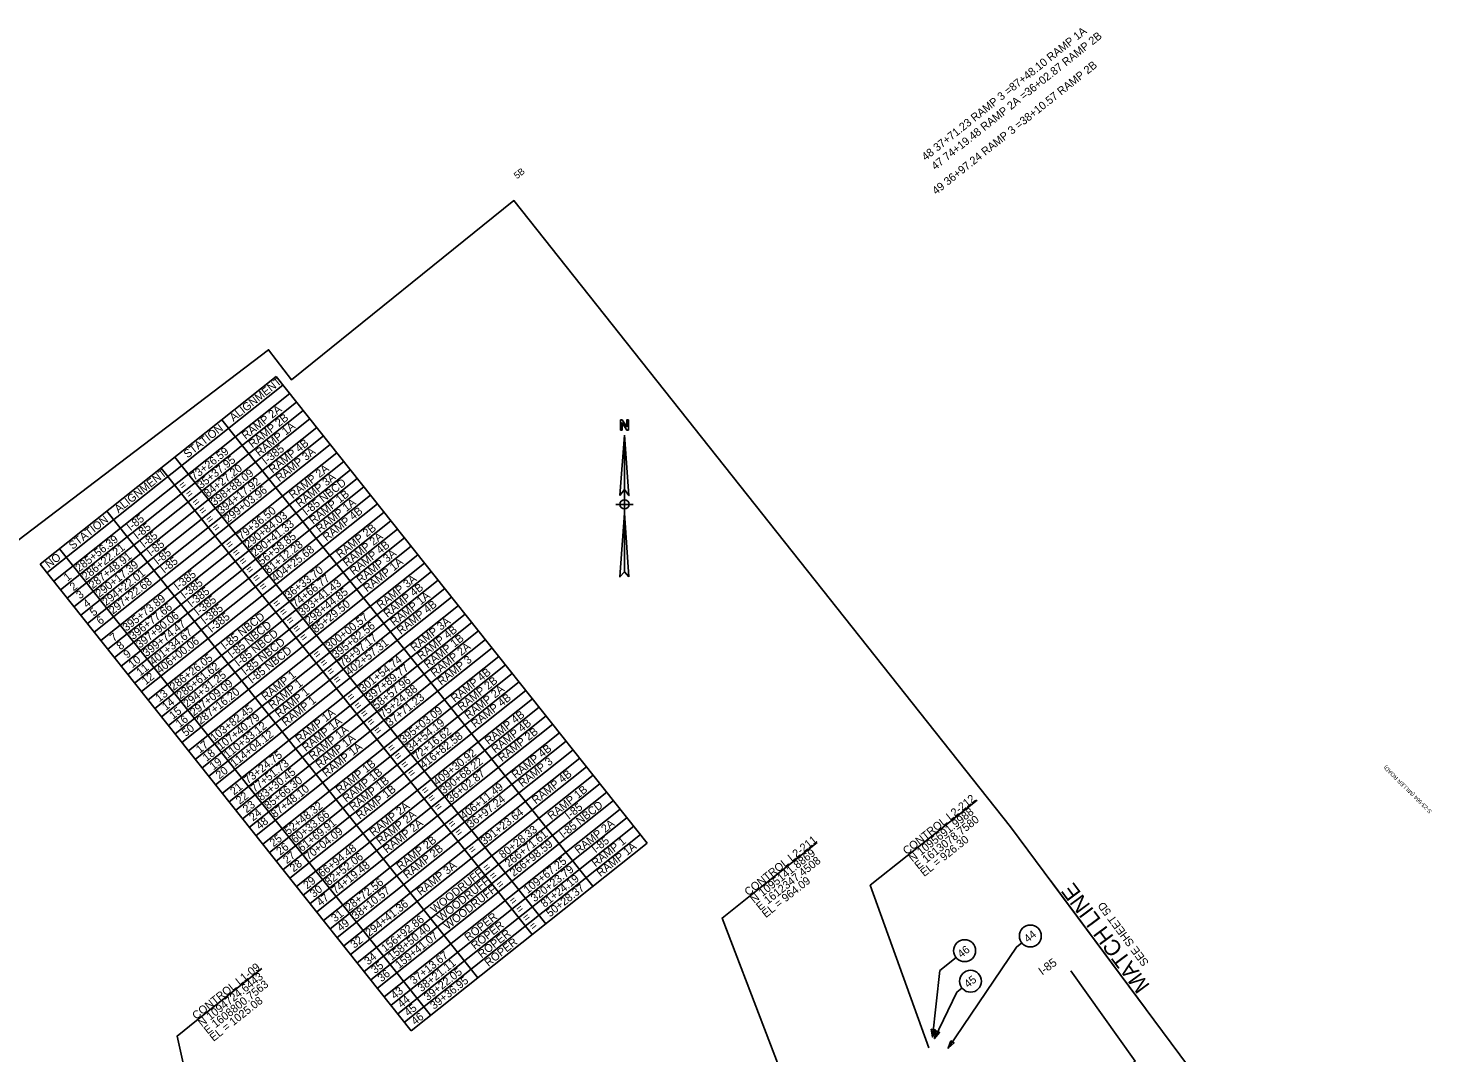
# Model space of a CAD drawing. Extents: x 1600294 to 1616097, y 1087057 to 1101809.
# Drawn here: x 1607677 to 1616097, y 1095661 to 1101809 of the extents above; entities that cross this region are included whole.
import ezdxf

# ---------------------------------------------------------------- set-up
doc = ezdxf.new("R2010")
doc.units = 0
for name, color, linetype in [('LABEL', 7, 'Continuous'), ('Level 1', 7, 'Continuous'), ('Plan_Clip', 7, 'Continuous'), ('RD_SHT_Bndy', 7, 'Continuous'), ('RD_SHT_MatchLine', 7, 'Continuous'), ('RD_SHT_TX', 7, 'Continuous'), ('RD_TX_Misc2', 7, 'Continuous'), ('RD_TX_RoadID', 7, 'Continuous')]:
    doc.layers.add(name, color=color, linetype=linetype)

msp = doc.modelspace()

# ---------------------------------------------------------------- linework, layer by layer
at = {"layer": 'LABEL'}
for points in [[(1613637.3, 1096321.6), (1613605.4, 1096296.3), (1613195.5, 1095689.7)], [(1613242.8, 1096233.5), (1613144.8, 1096155.6), (1613100.8, 1095756.4)], [(1613278.5, 1096050.3), (1613246.6, 1096025), (1613112.8, 1095747.6)]]:
    msp.add_lwpolyline(points, dxfattribs=at)
for points in [[(1613093.6, 1095803.4), (1613100.8, 1095756.4), (1613118, 1095800.7)], [(1613121.6, 1095794.2), (1613112.8, 1095747.6), (1613143.8, 1095783.6)], [(1613211, 1095734.7), (1613195.5, 1095689.7), (1613231.4, 1095720.9)]]:
    msp.add_lwpolyline(points, close=True, dxfattribs=at)
for centre in [(1613688.7, 1096362.5), (1613294.2, 1096274.4), (1613329.9, 1096091.2)]:
    msp.add_circle(centre, 65.7, dxfattribs=at)
at = {"layer": 'Level 1'}
for p, q in [((1611253.9, 1099366.7), (1611226.5, 1099004.2)), ((1611253.9, 1099041.4), (1611226.5, 1099004.2)), ((1611253.9, 1099041.4), (1611253.9, 1098898.7)), ((1611306.1, 1098951.6), (1611202.3, 1098951.6)), ((1611253.9, 1098898.7), (1611281.2, 1098516)), ((1611281.2, 1098516), (1611253.9, 1098546.6))]:
    msp.add_line(p, q, dxfattribs=at)
msp.add_lwpolyline([(1611277.4, 1099397.3), (1611267.6, 1099397.3), (1611240.2, 1099441.1), (1611240.2, 1099434.5), (1611240.2, 1099397.3), (1611230.4, 1099397.3), (1611230.4, 1099458), (1611240.2, 1099458), (1611267.6, 1099417.6), (1611267.6, 1099420.8), (1611267.6, 1099458), (1611277.4, 1099458), (1611277.4, 1099397.3)], dxfattribs=at)
for points in [[(1611253.9, 1099366.7), (1611281.2, 1099004.2), (1611253.9, 1099041.4)], [(1611253.9, 1098898.7), (1611253.9, 1098546.6), (1611226.5, 1098516)]]:
    msp.add_lwpolyline(points, close=True, dxfattribs=at)
msp.add_circle((1611254.2, 1098951.6), 27.6, dxfattribs=at)
at = {"layer": 'Plan_Clip'}
msp.add_lwpolyline([(1600293.9, 1092641.5), (1602343.7, 1094579.4), (1605167, 1096872.5), (1609119.4, 1099879.5), (1609257.5, 1099698.1), (1610590.9, 1100773.5), (1613569.3, 1097017.7), (1614735.8, 1095448.6), (1612219.9, 1092822.8), (1611099.3, 1092347), (1604705.4, 1087056.6)], close=True, dxfattribs=at)
at = {"layer": 'RD_SHT_MatchLine'}
msp.add_line((1614379.1, 1095928.4), (1613808.6, 1096695.9), dxfattribs=at)
at = {"layer": 'RD_SHT_TX'}
for p, q in [((1613369.6, 1097178), (1612949.9, 1096844.1)), ((1612410.7, 1096924.3), (1611999.8, 1096597.4)), ((1609079.9, 1096167.9), (1608687.5, 1095855.7))]:
    msp.add_line(p, q, dxfattribs=at)
for points in [[(1612949.9, 1096844.1), (1612727.9, 1096667.5), (1613078.8, 1095692)], [(1611999.8, 1096597.4), (1611839.6, 1096470), (1612347.5, 1095141.9)], [(1614184.5, 1095506.8), (1614316.5, 1095611.8), (1613931.7, 1096153.5)], [(1608687.5, 1095855.7), (1608570.6, 1095762.7), (1608800.8, 1094724.6)]]:
    msp.add_lwpolyline(points, dxfattribs=at)
at = {"layer": 'RD_TX_Misc2'}
for p, q in [((1607749.8, 1098592.3), (1609165.3, 1099718.2)), ((1607790.3, 1098541.4), (1609205.7, 1099667.3)), ((1609165.3, 1099718.2), (1611390.7, 1096920.3)), ((1607830.7, 1098490.6), (1609246.2, 1099616.4)), ((1607871.2, 1098439.7), (1609286.6, 1099565.6)), ((1607911.7, 1098388.8), (1609327.1, 1099514.7)), ((1607952.1, 1098338), (1609367.6, 1099463.8)), ((1607992.6, 1098287.1), (1609408, 1099413)), ((1608839.7, 1099459.2), (1611065.1, 1096661.3)), ((1608033.1, 1098236.2), (1609448.5, 1099362.1)), ((1608073.5, 1098185.3), (1609489, 1099311.2)), ((1608114, 1098134.5), (1609529.4, 1099260.3)), ((1608154.4, 1098083.6), (1609569.9, 1099209.5)), ((1608474.7, 1099168.9), (1610700.1, 1096371)), ((1608556.4, 1099233.9), (1610781.9, 1096436.1)), ((1608194.9, 1098032.7), (1609610.3, 1099158.6)), ((1608235.4, 1097981.9), (1609650.8, 1099107.7)), ((1608275.8, 1097931), (1609691.3, 1099056.9)), ((1608316.3, 1097880.1), (1609731.7, 1099006)), ((1608149.1, 1098909.9), (1610374.5, 1096112)), ((1608356.8, 1097829.3), (1609772.2, 1098955.1)), ((1608397.2, 1097778.4), (1609812.7, 1098904.3)), ((1608437.7, 1097727.5), (1609853.1, 1098853.4)), ((1608478.1, 1097676.7), (1609893.6, 1098802.5)), ((1608518.6, 1097625.8), (1609934, 1098751.7)), ((1607865.8, 1098684.6), (1610091.3, 1095886.8)), ((1608559.1, 1097574.9), (1609974.5, 1098700.8)), ((1607749.8, 1098592.3), (1609975.3, 1095794.5)), ((1608599.5, 1097524), (1610015, 1098649.9)), ((1608640, 1097473.2), (1610055.4, 1098599)), ((1608680.5, 1097422.3), (1610095.9, 1098548.2)), ((1608720.9, 1097371.4), (1610136.4, 1098497.3)), ((1608761.4, 1097320.6), (1610176.8, 1098446.4)), ((1608801.9, 1097269.7), (1610217.3, 1098395.6)), ((1608842.3, 1097218.8), (1610257.8, 1098344.7)), ((1608882.8, 1097168), (1610298.2, 1098293.8)), ((1608923.2, 1097117.1), (1610338.7, 1098243)), ((1608963.7, 1097066.2), (1610379.1, 1098192.1)), ((1609004.2, 1097015.3), (1610419.6, 1098141.2)), ((1609044.6, 1096964.5), (1610460.1, 1098090.3)), ((1609085.1, 1096913.6), (1610500.5, 1098039.5)), ((1609125.6, 1096862.7), (1610541, 1097988.6)), ((1609166, 1096811.9), (1610581.5, 1097937.7)), ((1609206.5, 1096761), (1610621.9, 1097886.9)), ((1609246.9, 1096710.1), (1610662.4, 1097836)), ((1609287.4, 1096659.3), (1610702.8, 1097785.1)), ((1609327.9, 1096608.4), (1610743.3, 1097734.3)), ((1609368.3, 1096557.5), (1610783.8, 1097683.4)), ((1609408.8, 1096506.6), (1610824.2, 1097632.5)), ((1609449.3, 1096455.8), (1610864.7, 1097581.6)), ((1609489.7, 1096404.9), (1610905.2, 1097530.8)), ((1609530.2, 1096354), (1610945.6, 1097479.9)), ((1609570.6, 1096303.2), (1610986.1, 1097429)), ((1609611.1, 1096252.3), (1611026.5, 1097378.2)), ((1609651.6, 1096201.4), (1611067, 1097327.3)), ((1609692, 1096150.6), (1611107.5, 1097276.4)), ((1609732.5, 1096099.7), (1611147.9, 1097225.6)), ((1609773, 1096048.8), (1611188.4, 1097174.7)), ((1609813.4, 1095997.9), (1611228.9, 1097123.8)), ((1609853.9, 1095947.1), (1611269.3, 1097072.9)), ((1609894.4, 1095896.2), (1611309.8, 1097022.1)), ((1609934.8, 1095845.3), (1611350.3, 1096971.2)), ((1609975.3, 1095794.5), (1611390.7, 1096920.3))]:
    msp.add_line(p, q, dxfattribs=at)

# ---------------------------------------------------------------- texts
at = {"layer": 'LABEL'}
for s, p in [('44', (1613673.6, 1096320.2)), ('46', (1613274.7, 1096228.5)), ('45', (1613314.8, 1096048.9))]:
    msp.add_text(s, height=47.52, rotation=38.4995, dxfattribs=at).set_placement(p)
at = {"layer": 'RD_SHT_Bndy'}
msp.add_text('5B', height=40, rotation=38.4995, dxfattribs=at).set_placement((1610609.8, 1100901.4))
at = {"layer": 'RD_SHT_MatchLine'}
for s, height, p in [('MATCH LINE', 96, (1614409.2, 1096065.4)), ('SEE SHEET 5D', 48, (1614401.8, 1096203.3))]:
    msp.add_text(s, height=height, rotation=126.62559, dxfattribs=at).set_placement(p)
at = {"layer": 'RD_SHT_TX'}
for s, p in [('48 37+71.23 RAMP 3 =87+48.10 RAMP 1A', (1613060.3, 1101010.2)), ('47 74+19.48 RAMP 2A =36+02.87 RAMP 2B', (1613118.6, 1100954.6)), ('49 36+97.24 RAMP 3 =38+10.57 RAMP 2B', (1613123.3, 1100806.4)), ('CONTROL L2-212', (1612947.4, 1096847.3)), ('N 1095691.9988', (1612982.3, 1096803.4)), ('E 1613078.7580', (1613017.1, 1096759.6)), ('CONTROL L2-211', (1611997.3, 1096600.5)), ('EL = 926.30', (1613052, 1096715.8)), ('N 1095141.8869', (1612032.1, 1096556.7)), ('E 1612347.4508', (1612067, 1096512.9)), ('EL = 964.09', (1612101.9, 1096469.1)), ('CONTROL L1-09', (1608685, 1095858.8)), ('N 1094724.6443', (1608719.8, 1095815)), ('E 1608800.7563', (1608754.7, 1095771.2)), ('EL = 1025.08', (1608789.5, 1095727.3))]:
    msp.add_text(s, height=48, rotation=38.4995, dxfattribs=at).set_placement(p)
at = {"layer": 'RD_TX_Misc2'}
for s, p in [('ALIGNMENT', (1608909.2, 1099445.8)), ('RAMP 2A', (1608982.6, 1099338.5)), ('RAMP 2B', (1609023, 1099287.6)), ('STATION', (1608633.9, 1099226.8)), ('RAMP 1A', (1609063.5, 1099236.7)), ('RAMP 4B', (1609144.4, 1099135)), ('73+26.59', (1608674.3, 1099093.3)), ('35+37.95', (1608714.8, 1099042.4)), ('I-385', (1609104, 1099185.8)), ('RAMP 3A', (1609184.9, 1099084.1)), ('ALIGNMENT', (1608219.2, 1098897)), ('84+27.20', (1608755.2, 1098991.5)), ('398+88.09', (1608795.7, 1098940.7)), ('RAMP 2A', (1609265.8, 1098982.4)), ('=', (1608603.7, 1099037.5)), ('394+17.92', (1608836.2, 1098889.8)), ('RAMP 3A', (1609306.3, 1098931.5)), ('I-85 NBCD', (1609346.7, 1098880.6)), ('=', (1608644.1, 1098986.7)), ('299+03.96', (1608876.6, 1098838.9)), ('RAMP 1B', (1609387.2, 1098829.8)), ('=', (1608684.5, 1098935.9)), ('=', (1608724.3, 1098885.9)), ('79+36.50', (1608957.6, 1098737.2)), ('290+84.03', (1608998, 1098686.3)), ('RAMP 1A', (1609427.7, 1098778.9)), ('RAMP 4B', (1609468.1, 1098728)), ('STATION', (1607944.7, 1098678.6)), ('I-85', (1608292, 1098789.2)), ('I-85', (1608332.5, 1098738.3)), ('=', (1608765.9, 1098833.6)), ('=', (1608805.1, 1098784.2)), ('290+41.33', (1609038.5, 1098635.4)), ('RAMP 2B', (1609549, 1098626.3)), ('285+56.39', (1607983.7, 1098544)), ('I-85', (1608372.9, 1098687.4)), ('I-85', (1608413.4, 1098636.5)), ('56+58.85', (1609078.9, 1098584.6)), ('RAMP 2A', (1609589.5, 1098575.4)), ('286+22.21', (1608023.5, 1098494)), ('287+48.91', (1608064.7, 1098442.2)), ('I-85', (1608453.8, 1098585.7)), ('=', (1608885.8, 1098682.8)), ('=', (1608925.8, 1098632.5)), ('81+12.28', (1609119.4, 1098533.7)), ('404+25.68', (1609159.9, 1098482.8)), ('RAMP 4B', (1609630, 1098524.5)), ('RAMP 3A', (1609670.4, 1098473.7)), ('NO', (1607803.3, 1098566.2)), ('290+17.39', (1608105.1, 1098391.4)), ('I-85', (1608494.3, 1098534.8)), ('=', (1608966.2, 1098581.7)), ('=', (1609006.3, 1098531.4)), ('36+33.70', (1609240.8, 1098381.1)), ('RAMP 1A', (1609710.9, 1098422.8)), ('1', (1607913.7, 1098487.6)), ('294+22.01', (1608145.6, 1098340.5)), ('297+22.68', (1608186.1, 1098289.6)), ('I-385', (1608575.2, 1098433.1)), ('I-385', (1608615.7, 1098382.2)), ('=', (1609046.7, 1098480.6)), ('74+66.77', (1609281.3, 1098330.2)), ('393+41.43', (1609321.7, 1098279.3)), ('RAMP 3A', (1609791.8, 1098321.1)), ('2', (1607949.7, 1098430)), ('3', (1607988.6, 1098381.1)), ('395+73.89', (1608267, 1098187.9)), ('I-385', (1608656.2, 1098331.3)), ('I-385', (1608696.6, 1098280.5)), ('=', (1609086.7, 1098430.2)), ('298+44.85', (1609362.2, 1098228.5)), ('RAMP 4B', (1609832.3, 1098270.2)), ('RAMP 1A', (1609872.7, 1098219.3)), ('4', (1608029.9, 1098328.5)), ('5', (1608070.6, 1098277.8)), ('396+77.66', (1608307.4, 1098137)), ('I-385', (1608737.1, 1098229.6)), ('=', (1609168, 1098328)), ('=', (1609208.4, 1098277.2)), ('85+29.50', (1609402.7, 1098177.6)), ('RAMP 4B', (1609913.2, 1098168.4)), ('6', (1608110.4, 1098227.3)), ('397+90.06', (1608347.9, 1098086.1)), ('399+74.47', (1608388.4, 1098035.3)), ('I-385', (1608777.5, 1098178.7)), ('I-85 NBCD', (1608858.5, 1098077)), ('I-85 NBCD', (1608898.9, 1098026.1)), ('=', (1609248.8, 1098226.4)), ('300+00.57', (1609483.6, 1098075.9)), ('395+82.56', (1609524, 1098025)), ('RAMP 3A', (1609994.1, 1098066.7)), ('7', (1608190.8, 1098125.3)), ('401+34.67', (1608428.8, 1097984.4)), ('406+00.06', (1608469.3, 1097933.5)), ('I-85 NBCD', (1608939.4, 1097975.2)), ('=', (1609288.8, 1098176.1)), ('=', (1609329.3, 1098125.2)), ('78+97.17', (1609564.5, 1097974.1)), ('RAMP 4B', (1610034.6, 1098015.8)), ('RAMP 1B', (1610075.1, 1097965)), ('8', (1608231, 1098075.9)), ('9', (1608271.6, 1098025.2)), ('I-85 NBCD', (1608979.9, 1097924.4)), ('I-85 NBCD', (1609020.3, 1097873.5)), ('=', (1609410, 1098023.7)), ('402+57.31', (1609605, 1097923.3)), ('RAMP 2A', (1610115.5, 1097914.1)), ('10', (1608302, 1097967.1)), ('11', (1608349.9, 1097919.8)), ('286+26.05', (1608550.2, 1097831.8)), ('286+61.62', (1608590.7, 1097780.9)), ('=', (1609451.2, 1097972)), ('301+54.74', (1609685.9, 1097821.5)), ('397+89.77', (1609726.4, 1097770.7)), ('RAMP 3', (1610156, 1097863.2)), ('12', (1608382.8, 1097866.1)), ('294+31.25', (1608631.2, 1097730.1)), ('297+09.09', (1608671.6, 1097679.2)), ('RAMP 1', (1609101.2, 1097771.8)), ('RAMP 1', (1609141.7, 1097720.9)), ('=', (1609491.9, 1097920.8)), ('=', (1609531.3, 1097871.3)), ('58+57.96', (1609766.8, 1097719.8)), ('RAMP 4B', (1610236.9, 1097761.5)), ('RAMP 2B', (1610277.4, 1097710.6)), ('13', (1608464.2, 1097763.7)), ('287+16.20', (1608712.1, 1097628.3)), ('RAMP 1', (1609182.2, 1097670)), ('=', (1609613.5, 1097767.9)), ('75+24.88', (1609807.3, 1097668.9)), ('37+71.23', (1609847.7, 1097618)), ('RAMP 2A', (1610317.8, 1097659.7)), ('RAMP 4B', (1610358.3, 1097608.9)), ('14', (1608504, 1097713.1)), ('15', (1608546.6, 1097659.9)), ('103+82.45', (1608793, 1097526.6)), ('RAMP 1', (1609222.6, 1097619.1)), ('=', (1609655, 1097715.8)), ('395+03.09', (1609928.7, 1097516.3)), ('16', (1608586, 1097609.9)), ('107+40.79', (1608833.5, 1097475.7)), ('110+33.12', (1608873.9, 1097424.8)), ('RAMP 1A', (1609303.6, 1097517.4)), ('RAMP 1A', (1609344, 1097466.5)), ('=', (1609693.2, 1097667.7)), ('=', (1609733.6, 1097616.9)), ('34+54.19', (1609969.1, 1097465.4)), ('RAMP 4B', (1610439.2, 1097507.1)), ('RAMP 4B', (1610479.7, 1097456.3)), ('50', (1608623, 1097556.2)), ('114+04.12', (1608914.4, 1097374)), ('RAMP 1A', (1609384.5, 1097415.7)), ('RAMP 1A', (1609425, 1097364.8)), ('=', (1609774.1, 1097566)), ('72+16.62', (1610009.6, 1097414.6)), ('416+82.58', (1610050.1, 1097363.7)), ('RAMP 2B', (1610520.2, 1097405.4)), ('17', (1608707.3, 1097456.5)), ('18', (1608747.9, 1097406.5)), ('RAMP 1A', (1609465.4, 1097313.9)), ('=', (1609856.3, 1097462.7)), ('409+30.92', (1610131, 1097262)), ('RAMP 4B', (1610601.1, 1097303.7)), ('19', (1608788.9, 1097355.3)), ('73+24.75', (1608995.3, 1097272.2)), ('77+51.73', (1609035.8, 1097221.4)), ('RAMP 1B', (1609546.3, 1097212.2)), ('=', (1609895.6, 1097413.3)), ('=', (1609936.4, 1097362)), ('390+68.22', (1610171.4, 1097211.1)), ('RAMP 3', (1610641.5, 1097252.8)), ('20', (1608825.2, 1097301.9)), ('83+30.45', (1609076.2, 1097170.5)), ('85+66.30', (1609116.7, 1097119.6)), ('RAMP 1B', (1609586.8, 1097161.3)), ('RAMP 1B', (1609627.3, 1097110.4)), ('=', (1609976.8, 1097311.2)), ('36+02.87', (1610211.9, 1097160.2)), ('RAMP 4B', (1610722.5, 1097151)), ('21', (1608912.4, 1097205.1)), ('22', (1608946.9, 1097149.5)), ('87+48.10', (1609157.2, 1097068.7)), ('RAMP 1B', (1609667.7, 1097059.6)), ('=', (1610058.9, 1097207.9)), ('406+11.49', (1610292.8, 1097058.5)), ('RAMP 1B', (1610816.4, 1097057.3)), ('23', (1608987.7, 1097098.1)), ('52+48.32', (1609238.1, 1096967)), ('RAMP 2A', (1609748.7, 1096957.8)), ('=', (1610097.1, 1097160)), ('=', (1610137.5, 1097109.1)), ('36+97.24', (1610333.3, 1097007.6)), ('I-85 NBCD', (1610886.4, 1096946.7)), ('I-85', (1610921.1, 1097058.9)), ('24', (1609026.3, 1097049)), ('48', (1609066.8, 1096998.2)), ('60+33.66', (1609278.6, 1096916.1)), ('61+69.91', (1609319, 1096865.3)), ('RAMP 2A', (1609789.1, 1096907)), ('RAMP 2A', (1609829.6, 1096856.1)), ('391+23.64', (1610414.2, 1096905.9)), ('RAMP 2A', (1610978.9, 1096853)), ('25', (1609149.2, 1096894.9)), ('70+04.09', (1609359.5, 1096814.4)), ('=', (1610219.5, 1097006.1)), ('=', (1610260, 1096955.2)), ('80+28.33', (1610524.9, 1096824.8)), ('266+71.61', (1610559.9, 1096773.7)), ('26', (1609189, 1096844.4)), ('66+94.48', (1609440.4, 1096712.7)), ('RAMP 2B', (1609910.5, 1096754.4)), ('RAMP 2B', (1609951, 1096703.5)), ('=', (1610341.4, 1096852.8)), ('266+98.59', (1610589.8, 1096716.2)), ('RAMP 1', (1611080.4, 1096774.4)), ('I-85', (1611081.1, 1096857.8)), ('RAMP 1A', (1611110.5, 1096715.3)), ('27', (1609229.4, 1096792.7)), ('28', (1609269.6, 1096743.2)), ('82+52.06', (1609480.9, 1096661.8)), ('74+19.48', (1609521.3, 1096610.9)), ('RAMP 3A', (1610031.9, 1096601.7)), ('109+67.25', (1610673, 1096613.9)), ('WOODRUFF', (1610115, 1096496.9)), ('WOODRUFF', (1610154.2, 1096447.7)), ('=', (1610427.4, 1096744.7)), ('=', (1610466.8, 1096695.2)), ('320+23.79', (1610715.8, 1096564)), ('81+24.19', (1610775.4, 1096530.9)), ('29', (1609350.9, 1096641.5)), ('30', (1609391.1, 1096590.4)), ('28+72.56', (1609602.3, 1096509.2)), ('38+10.57', (1609642.7, 1096458.3)), ('WOODRUFF', (1610194, 1096397.6)), ('=', (1610507.5, 1096644)), ('50+28.37', (1610807.9, 1096473.6)), ('47', (1609431.1, 1096539.2)), ('294+41.36', (1609723.7, 1096356.6)), ('=', (1610586.1, 1096545.2)), ('31', (1609518.4, 1096443.3)), ('156+92.86', (1609818.5, 1096263.6)), ('ROPER', (1610317.6, 1096328.3)), ('=', (1610625.4, 1096495.8)), ('=', (1610666.1, 1096444.6)), ('49', (1609552.8, 1096387.6)), ('158+50.40', (1609858.2, 1096213.8)), ('159+41.07', (1609902.2, 1096164.9)), ('ROPER', (1610357.5, 1096278.2)), ('ROPER', (1610398, 1096227.3)), ('=', (1610706.6, 1096393.8)), ('32', (1609634.2, 1096285.4)), ('ROPER', (1610438.5, 1096176.4)), ('34', (1609716.6, 1096185.5)), ('37+13.67', (1609991.1, 1096069.9)), ('38+21.11', (1610037, 1096024.7)), ('35', (1609758, 1096133.8)), ('36', (1609797, 1096084.3)), ('39+22.05', (1610074.5, 1095971.4)), ('43', (1609875.9, 1095980.8)), ('39+36.95', (1610112.2, 1095919.5)), ('44', (1609916.8, 1095928.8)), ('45', (1609957.4, 1095878.1)), ('46', (1609998.8, 1095825.6))]:
    msp.add_text(s, height=48, rotation=38.4995, dxfattribs=at).set_placement(p)
at = {"layer": 'RD_TX_RoadID'}
for s, height, rotation, p in [('S-23-564 (MILLER ROAD)', 24, 135.10354, (1616098.8, 1097111.5)), ('I-85', 50, 36.05854, (1613759.5, 1096125))]:
    msp.add_text(s, height=height, rotation=rotation, dxfattribs=at).set_placement(p)

doc.saveas('drawing.dxf')
